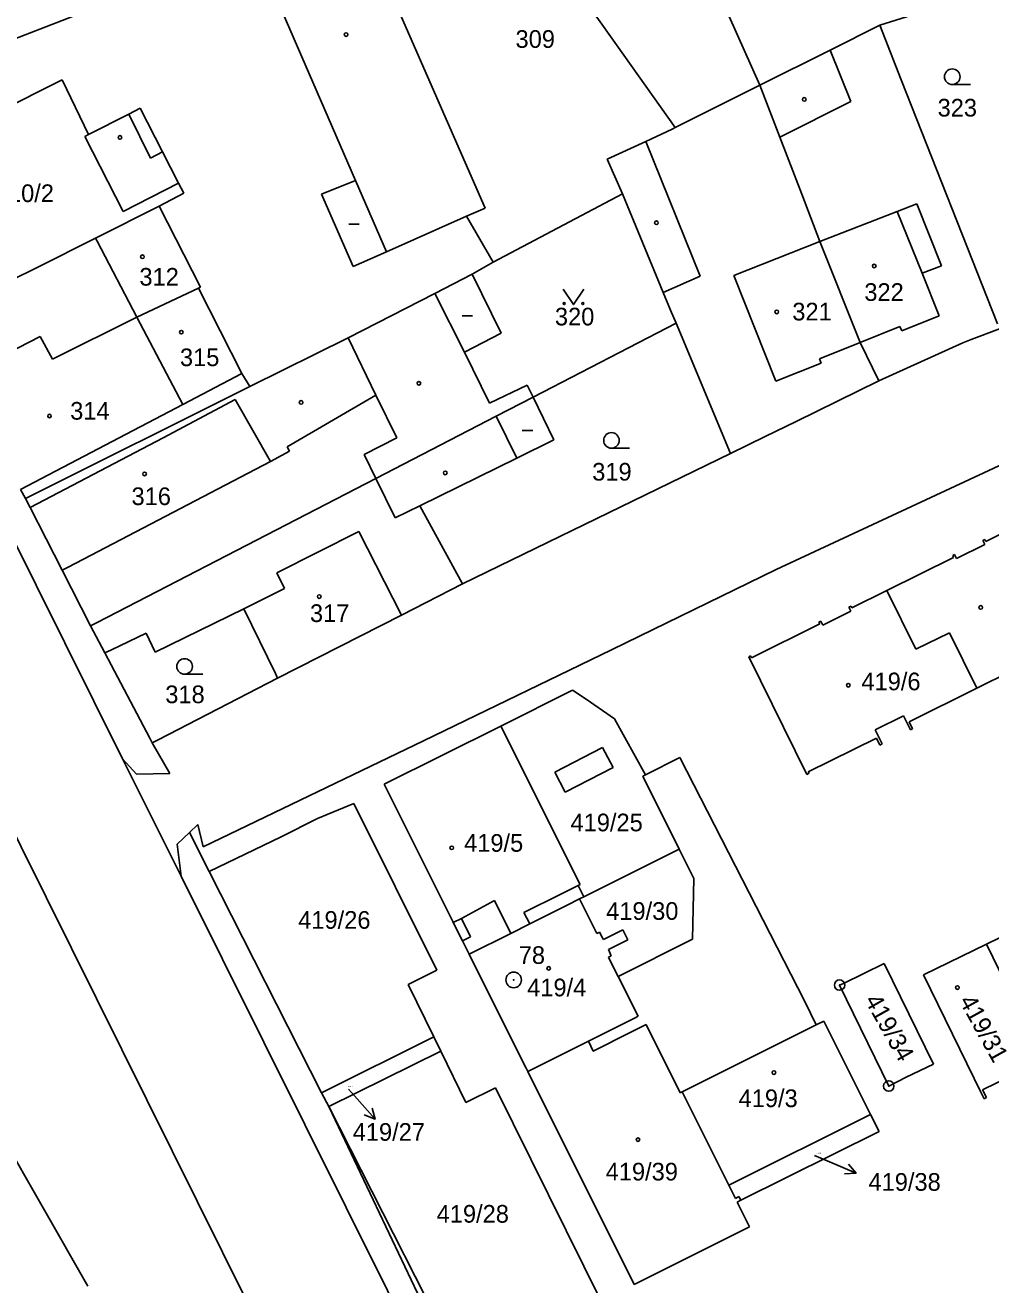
# Model space of a CAD drawing. Extents: x -736345 to -729997, y -1130177 to -1122501.
# Drawn here: x -733645.7 to -733552.8, y -1126760.8 to -1126639.6 of the extents above; entities that cross this region are included whole.
import ezdxf

# ---------------------------------------------------------------- set-up
doc = ezdxf.new("R2010")
doc.units = 0
for name, color, linetype in [('Vrstva 1', 7, 'Continuous'), ('Vrstva 16', 7, 'Continuous'), ('Vrstva 17', 7, 'Continuous'), ('Vrstva 18', 7, 'Continuous'), ('Vrstva 19', 7, 'Continuous'), ('Vrstva 25', 7, 'Continuous'), ('Vrstva 4', 7, 'Continuous')]:
    doc.layers.add(name, color=color, linetype=linetype)

msp = doc.modelspace()

# ---------------------------------------------------------------- linework, layer by layer
at = {"layer": 'Vrstva 1'}
for points in [[(-733601.42, -1126657.16), (-733617.83, -1126619.63)], [(-733582.38, -1126628.77), (-733575, -1126645.33)], [(-733583.13, -1126649.42), (-733597.4, -1126629.25)], [(-733556.36, -1126637.34), (-733563.45, -1126639.57)], [(-733563.45, -1126639.57), (-733568.23, -1126641.96)], [(-733563.45, -1126639.57), (-733561.38, -1126644.83)], [(-733568.23, -1126641.96), (-733575, -1126645.33)], [(-733642.11, -1126644.82), (-733660.73, -1126654.16)], [(-733639.58, -1126650.08), (-733642.11, -1126644.82)], [(-733575, -1126645.33), (-733583.13, -1126649.42)], [(-733575, -1126645.33), (-733573.08, -1126650.34)], [(-733561.38, -1126644.83), (-733552.13, -1126668.3)], [(-733635.72, -1126648.11), (-733639.58, -1126650.08)], [(-733634.61, -1126647.54), (-733635.72, -1126648.11)], [(-733632.46, -1126651.75), (-733634.61, -1126647.54)], [(-733583.13, -1126649.42), (-733583.44, -1126649.57)], [(-733585.97, -1126650.76), (-733589.67, -1126652.44)], [(-733583.44, -1126649.57), (-733585.97, -1126650.76)], [(-733573.08, -1126650.34), (-733570.96, -1126655.81)], [(-733630.92, -1126654.75), (-733632.46, -1126651.75)], [(-733589.67, -1126652.44), (-733588.21, -1126655.8)], [(-733664.04, -1126654.46), (-733636.32, -1126710.15)], [(-733630.42, -1126655.72), (-733630.92, -1126654.75)], [(-733632.78, -1126656.97), (-733630.42, -1126655.72)], [(-733600.64, -1126662.36), (-733588.21, -1126655.8)], [(-733588.21, -1126655.8), (-733584.3, -1126665.28)], [(-733570.96, -1126655.81), (-733569.22, -1126660.36)], [(-733638.9, -1126660.06), (-733632.78, -1126656.97)], [(-733632.78, -1126656.97), (-733628.8, -1126664.77)], [(-733601.42, -1126657.16), (-733603.21, -1126657.94)], [(-733603.21, -1126657.94), (-733600.64, -1126662.36)], [(-733644.46, -1126662.84), (-733638.9, -1126660.06)], [(-733638.76, -1126660.33), (-733638.9, -1126660.06)], [(-733634.94, -1126667.64), (-733638.76, -1126660.33)], [(-733569.22, -1126660.36), (-733565.34, -1126670.1)], [(-733647.06, -1126664.14), (-733644.46, -1126662.84)], [(-733600.64, -1126662.36), (-733602.67, -1126663.52)], [(-733602.67, -1126663.52), (-733606.27, -1126665.37)], [(-733602.67, -1126663.52), (-733599.87, -1126669.2)], [(-733629, -1126664.87), (-733634.94, -1126667.64)], [(-733628.8, -1126664.77), (-733629, -1126664.87)], [(-733624.82, -1126673.08), (-733629, -1126664.87)], [(-733584.3, -1126665.28), (-733583.58, -1126666.98)], [(-733606.27, -1126665.37), (-733614.62, -1126669.65)], [(-733634.94, -1126667.64), (-733630.52, -1126676.07)], [(-733583.58, -1126666.98), (-733583.04, -1126668.24)], [(-733583.04, -1126668.24), (-733596.81, -1126675.35)], [(-733583.04, -1126668.24), (-733577.83, -1126680.78)], [(-733554.65, -1126669.8), (-733551.94, -1126668.78)], [(-733614.62, -1126669.65), (-733624.06, -1126674.34)], [(-733599.87, -1126669.2), (-733603.42, -1126671.02)], [(-733565.34, -1126670.1), (-733563.55, -1126673.78)], [(-733563.55, -1126673.78), (-733555.47, -1126670.11)], [(-733555.47, -1126670.11), (-733554.65, -1126669.8)], [(-733603.42, -1126671.02), (-733600.99, -1126675.94)], [(-733630.52, -1126676.07), (-733624.82, -1126673.08)], [(-733624.82, -1126673.08), (-733624.06, -1126674.34)], [(-733571.51, -1126677.68), (-733563.55, -1126673.78)], [(-733624.06, -1126674.34), (-733645.66, -1126685.1)], [(-733600.99, -1126675.94), (-733597.37, -1126674.19)], [(-733597.37, -1126674.19), (-733596.81, -1126675.35)], [(-733596.81, -1126675.35), (-733600.37, -1126677.19)], [(-733594.82, -1126679.47), (-733596.81, -1126675.35)], [(-733600.37, -1126677.19), (-733611.95, -1126683.18)], [(-733574.49, -1126679.14), (-733571.51, -1126677.68)], [(-733598.38, -1126681.23), (-733594.82, -1126679.47)], [(-733577.83, -1126680.78), (-733574.49, -1126679.14)], [(-733547.38, -1126679.81), (-733573.41, -1126691.93)], [(-733603.59, -1126693.32), (-733577.83, -1126680.78)], [(-733607.71, -1126685.82), (-733598.38, -1126681.23)], [(-733611.95, -1126683.18), (-733638.77, -1126697.05)], [(-733646.12, -1126684.23), (-733645.66, -1126685.1)], [(-733645.66, -1126685.1), (-733645.21, -1126685.98)], [(-733603.59, -1126693.32), (-733607.71, -1126685.82)], [(-733645.21, -1126685.98), (-733642.13, -1126692)], [(-733553.26, -1126689.24), (-733546.65, -1126685.95)], [(-733556.06, -1126690.89), (-733553.34, -1126689.54)], [(-733553.53, -1126689.15), (-733553.35, -1126689.06)], [(-733553.34, -1126689.54), (-733553.53, -1126689.15)], [(-733553.35, -1126689.06), (-733553.26, -1126689.24)], [(-733556.35, -1126690.77), (-733562.77, -1126693.96)], [(-733556.44, -1126690.59), (-733556.26, -1126690.5)], [(-733556.35, -1126690.77), (-733556.44, -1126690.59)], [(-733556.26, -1126690.5), (-733556.06, -1126690.89)], [(-733573.41, -1126691.93), (-733589.27, -1126699.67)], [(-733642.13, -1126692), (-733639.39, -1126697.37)], [(-733609.47, -1126696.33), (-733603.59, -1126693.32)], [(-733566.14, -1126695.63), (-733562.77, -1126693.96)], [(-733559.97, -1126699.61), (-733562.77, -1126693.96)], [(-733566.42, -1126695.55), (-733566.22, -1126695.45)], [(-733566.23, -1126695.95), (-733566.42, -1126695.55)], [(-733566.22, -1126695.45), (-733566.14, -1126695.63)], [(-733633.17, -1126699.89), (-733624.63, -1126695.73)], [(-733624.63, -1126695.73), (-733621.61, -1126701.93)], [(-733621.39, -1126702.39), (-733609.47, -1126696.33)], [(-733568.94, -1126697.3), (-733566.23, -1126695.95)], [(-733638.77, -1126697.05), (-733639.39, -1126697.37)], [(-733639.39, -1126697.37), (-733638.01, -1126699.97)], [(-733575.79, -1126700.43), (-733569.23, -1126697.17)], [(-733569.32, -1126696.99), (-733569.14, -1126696.9)], [(-733569.23, -1126697.17), (-733569.32, -1126696.99)], [(-733569.14, -1126696.9), (-733568.94, -1126697.3)], [(-733556.75, -1126698.02), (-733559.97, -1126699.61)], [(-733554.1, -1126703.36), (-733556.75, -1126698.02)], [(-733637.39, -1126699.67), (-733634.03, -1126698.06)], [(-733634.03, -1126698.06), (-733633.17, -1126699.89)], [(-733638.01, -1126699.97), (-733637.39, -1126699.67)], [(-733638.01, -1126699.97), (-733633.69, -1126708.18)], [(-733589.27, -1126699.67), (-733607.36, -1126708.43)], [(-733576.06, -1126700.34), (-733575.88, -1126700.25)], [(-733570.46, -1126711.65), (-733576.06, -1126700.34)], [(-733575.88, -1126700.25), (-733575.79, -1126700.43)], [(-733632.88, -1126708.32), (-733621.39, -1126702.39)], [(-733621.61, -1126701.93), (-733621.39, -1126702.39)], [(-733550.89, -1126701.76), (-733554.1, -1126703.36)], [(-733617, -1126777.14), (-733653.37, -1126703.96)], [(-733599.9, -1126707), (-733593.02, -1126703.56)], [(-733593.02, -1126703.56), (-733591.71, -1126704.4)], [(-733554.1, -1126703.36), (-733560.62, -1126706.59)], [(-733591.71, -1126704.4), (-733588.97, -1126706.31)], [(-733588.97, -1126706.31), (-733585.99, -1126711.69)], [(-733561.18, -1126706.03), (-733563.89, -1126707.38)], [(-733560.51, -1126707.38), (-733561.18, -1126706.03)], [(-733611.13, -1126712.61), (-733599.9, -1126707)], [(-733599.9, -1126707), (-733592.28, -1126722.24)], [(-733563.89, -1126707.38), (-733563.22, -1126708.72)], [(-733560.62, -1126706.59), (-733560.29, -1126707.27)], [(-733560.29, -1126707.27), (-733560.51, -1126707.38)], [(-733633.69, -1126708.18), (-733633.46, -1126708.62)], [(-733633.46, -1126708.62), (-733632.88, -1126708.32)], [(-733631.75, -1126711.56), (-733633.46, -1126708.62)], [(-733607.36, -1126708.43), (-733628.57, -1126718.64)], [(-733563.77, -1126708.16), (-733570.33, -1126711.41)], [(-733563.44, -1126708.83), (-733563.77, -1126708.16)], [(-733563.22, -1126708.72), (-733563.44, -1126708.83)], [(-733636.32, -1126710.15), (-733634.96, -1126711.62), (-733631.75, -1126711.56)], [(-733630.68, -1126721.44), (-733636.32, -1126710.15)], [(-733585.99, -1126711.69), (-733582.69, -1126710.04)], [(-733570.68, -1126733.52), (-733582.69, -1126710.04)], [(-733585.99, -1126711.69), (-733586.26, -1126711.82)], [(-733586.26, -1126711.82), (-733582.75, -1126718.85)], [(-733570.26, -1126711.55), (-733570.46, -1126711.65)], [(-733570.33, -1126711.41), (-733570.26, -1126711.55)], [(-733604.54, -1126725.8), (-733611.13, -1126712.61)], [(-733617.56, -1126715.9), (-733614.06, -1126714.44)], [(-733614.06, -1126714.44), (-733606.07, -1126730.5)], [(-733621.05, -1126717.67), (-733617.56, -1126715.9)], [(-733629.87, -1126717.24), (-733631.05, -1126718.36)], [(-733629.87, -1126717.24), (-733629.06, -1126716.46)], [(-733629.87, -1126717.24), (-733627.99, -1126721)], [(-733628.57, -1126718.64), (-733629.06, -1126716.46)], [(-733630.68, -1126721.44), (-733631.05, -1126718.36)], [(-733627.99, -1126721), (-733621.05, -1126717.67)], [(-733591.92, -1126723.44), (-733582.75, -1126718.85)], [(-733582.75, -1126718.85), (-733581.34, -1126721.67)], [(-733617.18, -1126742.29), (-733627.99, -1126721)], [(-733630.68, -1126721.44), (-733590.98, -1126801.18)], [(-733592.28, -1126722.24), (-733592.47, -1126722.34)], [(-733581.34, -1126721.67), (-733581.48, -1126727.52)], [(-733597.69, -1126724.95), (-733594.08, -1126723.14)], [(-733594.08, -1126723.14), (-733592.47, -1126722.34)], [(-733591.92, -1126723.44), (-733592.34, -1126723.64)], [(-733603.7, -1126725.51), (-733600.53, -1126723.8)], [(-733600.53, -1126723.8), (-733598.96, -1126726.95)], [(-733593.53, -1126724.24), (-733597.14, -1126726.05)], [(-733592.34, -1126723.64), (-733593.53, -1126724.24)], [(-733592.34, -1126723.64), (-733590.68, -1126726.96)], [(-733553.2, -1126727.99), (-733546.01, -1126724.49)], [(-733604.49, -1126725.9), (-733604.54, -1126725.8)], [(-733604.49, -1126725.9), (-733603.7, -1126725.51)], [(-733603.61, -1126727.66), (-733604.49, -1126725.9)], [(-733597.14, -1126726.05), (-733597.69, -1126724.95)], [(-733598.96, -1126726.95), (-733597.14, -1126726.05)], [(-733590.68, -1126726.96), (-733590.42, -1126726.83)], [(-733590.42, -1126726.83), (-733590.33, -1126727.01)], [(-733590.33, -1126727.01), (-733590.19, -1126727.27)], [(-733590.05, -1126727.55), (-733588.19, -1126726.62)], [(-733588.19, -1126726.62), (-733587.71, -1126727.58)], [(-733602.96, -1126728.95), (-733603.61, -1126727.66)], [(-733590.19, -1126727.27), (-733590.05, -1126727.55)], [(-733587.71, -1126727.58), (-733589.57, -1126728.51)], [(-733588.63, -1126731.09), (-733581.48, -1126727.52)], [(-733559.24, -1126730.93), (-733553.2, -1126727.99)], [(-733553.2, -1126727.99), (-733550.12, -1126734.31)], [(-733602.82, -1126729.23), (-733602.96, -1126728.95)], [(-733597.47, -1126739.93), (-733602.82, -1126729.23)], [(-733589.57, -1126728.51), (-733589.29, -1126729.11)], [(-733589.29, -1126729.11), (-733589.54, -1126729.25)], [(-733589.54, -1126729.25), (-733588.74, -1126730.87)], [(-733606.07, -1126730.5), (-733608.83, -1126731.88)], [(-733566.96, -1126731.76), (-733563.02, -1126729.84)], [(-733563.02, -1126729.84), (-733558.3, -1126739.53)], [(-733608.83, -1126731.88), (-733606.37, -1126736.9)], [(-733588.74, -1126730.87), (-733588.63, -1126731.09)], [(-733588.63, -1126731.09), (-733586.69, -1126734.93)], [(-733567.32, -1126731.93), (-733566.96, -1126731.76)], [(-733562.59, -1126741.64), (-733567.32, -1126731.93)], [(-733554.37, -1126740.92), (-733559.24, -1126730.93)], [(-733570.68, -1126733.52), (-733569.56, -1126735.75)], [(-733587.89, -1126735.53), (-733591.49, -1126737.34)], [(-733587.05, -1126735.11), (-733587.89, -1126735.53)], [(-733586.69, -1126734.93), (-733587.05, -1126735.11)], [(-733568.84, -1126735.39), (-733569.56, -1126735.75)], [(-733564.35, -1126744.37), (-733568.84, -1126735.39)], [(-733585.94, -1126735.73), (-733587.42, -1126736.47), (-733591.03, -1126738.28), (-733591.49, -1126737.34)], [(-733585.94, -1126735.73), (-733582.66, -1126742.3)], [(-733606.37, -1126736.9), (-733617.18, -1126742.29)], [(-733606.37, -1126736.9), (-733605.69, -1126738.29)], [(-733591.49, -1126737.34), (-733597.31, -1126740.25)], [(-733652.34, -1126738.71), (-733639.66, -1126760.9)], [(-733616.47, -1126743.62), (-733605.69, -1126738.29)], [(-733605.69, -1126738.29), (-733603.27, -1126743.24)], [(-733597.31, -1126740.25), (-733597.47, -1126739.93)], [(-733597.31, -1126740.25), (-733587.07, -1126760.73)], [(-733558.3, -1126739.53), (-733560.91, -1126740.8)], [(-733549.51, -1126740.02), (-733553.56, -1126742)], [(-733560.91, -1126740.8), (-733562.59, -1126741.64)], [(-733553.79, -1126742.11), (-733554.37, -1126740.92)], [(-733616.47, -1126743.62), (-733617.18, -1126742.29)], [(-733603.27, -1126743.24), (-733600.44, -1126741.82)], [(-733600.44, -1126741.82), (-733588.52, -1126765.83)], [(-733582.66, -1126742.3), (-733582.48, -1126742.21)], [(-733577.99, -1126751.19), (-733582.48, -1126742.21)], [(-733553.42, -1126742.87), (-733553.79, -1126742.11)], [(-733553.56, -1126742), (-733553.19, -1126742.76)], [(-733553.19, -1126742.76), (-733553.42, -1126742.87)], [(-733601.94, -1126772.22), (-733616.47, -1126743.62)], [(-733616.47, -1126743.62), (-733602.44, -1126773.11)], [(-733577.99, -1126751.19), (-733564.35, -1126744.37)], [(-733564.35, -1126744.37), (-733563.52, -1126746.02)], [(-733563.52, -1126746.02), (-733576.82, -1126752.64)], [(-733577.35, -1126752.46), (-733577.99, -1126751.19)], [(-733577, -1126752.28), (-733577.35, -1126752.46)], [(-733576.82, -1126752.64), (-733577, -1126752.28)], [(-733577.18, -1126752.82), (-733576.82, -1126752.64)], [(-733576.88, -1126753.4), (-733577.18, -1126752.82)], [(-733575.99, -1126755.18), (-733576.88, -1126753.4)], [(-733587.07, -1126760.73), (-733575.99, -1126755.18)]]:
    msp.add_lwpolyline(points, dxfattribs=at)
at = {"layer": 'Vrstva 16'}
for points in [[(-733614.58, -1126741.94), (-733614, -1126742.59)], [(-733569.72, -1126748.34), (-733568.5, -1126748.85)]]:
    msp.add_lwpolyline(points, dxfattribs=at)
at = {"layer": 'Vrstva 25'}
for points in [[(-733556.48, -1126645.27), (-733554.73, -1126645.27)], [(-733614.54, -1126658.72), (-733613.54, -1126658.72)], [(-733593.92, -1126664.95), (-733592.92, -1126666.45), (-733591.92, -1126664.95)], [(-733603.64, -1126667.52), (-733602.64, -1126667.52)], [(-733597.85, -1126678.55), (-733596.85, -1126678.55)], [(-733589.27, -1126680.27), (-733587.52, -1126680.27)], [(-733630.34, -1126702.02), (-733628.59, -1126702.02)], [(-733614, -1126742.59), (-733612.017, -1126744.84)], [(-733612.303, -1126743.759), (-733612.017, -1126744.84), (-733613.053, -1126744.42)], [(-733568.5, -1126748.85), (-733565.737, -1126750.017)], [(-733566.464, -1126749.167), (-733565.737, -1126750.017), (-733566.853, -1126750.088)]]:
    msp.add_lwpolyline(points, dxfattribs=at)
for centre, radius in [((-733614.8, -1126640.46), 0.175), ((-733556.48, -1126644.52), 0.75), ((-733570.72, -1126646.7), 0.175), ((-733636.56, -1126650.36), 0.175), ((-733584.94, -1126658.57), 0.175), ((-733634.4, -1126661.84), 0.175), ((-733563.99, -1126662.73), 0.175), ((-733593.82, -1126666.35), 0.1), ((-733592.02, -1126666.35), 0.1), ((-733573.37, -1126667.15), 0.175), ((-733630.66, -1126669.1), 0.175), ((-733607.8, -1126674.02), 0.175), ((-733619.13, -1126675.86), 0.175), ((-733643.34, -1126677.17), 0.175), ((-733589.27, -1126679.52), 0.75), ((-733634.19, -1126682.74), 0.175), ((-733605.26, -1126682.64), 0.175), ((-733617.39, -1126694.54), 0.175), ((-733553.74, -1126695.59), 0.175), ((-733630.34, -1126701.27), 0.75), ((-733566.48, -1126703.07), 0.175), ((-733604.64, -1126718.72), 0.175), ((-733598.68, -1126731.43), 0.75), ((-733595.31, -1126730.32), 0.175), ((-733598.68, -1126731.43), 0.032), ((-733567.32, -1126731.93), 0.5), ((-733567.32, -1126731.93), 0.032), ((-733555.98, -1126732.17), 0.175), ((-733573.64, -1126740.35), 0.175), ((-733562.59, -1126741.64), 0.5), ((-733562.59, -1126741.64), 0.032), ((-733586.72, -1126746.8), 0.175)]:
    msp.add_circle(centre, radius, dxfattribs=at)
at = {"layer": 'Vrstva 4'}
for points in [[(-733627.7, -1126622.7), (-733613.91, -1126654.5)], [(-733648.86, -1126641.72), (-733641.13, -1126638.72)], [(-733568.23, -1126641.96), (-733566.24, -1126646.91)], [(-733566.24, -1126646.91), (-733573.08, -1126650.34)], [(-733635.72, -1126648.11), (-733633.62, -1126652.34)], [(-733639.95, -1126650.27), (-733639.58, -1126650.08)], [(-733636.26, -1126657.48), (-733639.95, -1126650.27)], [(-733585.97, -1126650.76), (-733580.73, -1126663.7)], [(-733633.62, -1126652.34), (-733632.46, -1126651.75)], [(-733630.92, -1126654.75), (-733636.26, -1126657.48)], [(-733613.91, -1126654.5), (-733617.18, -1126655.83)], [(-733613.91, -1126654.5), (-733610.93, -1126661.37)], [(-733617.18, -1126655.83), (-733614.11, -1126662.77)], [(-733559.88, -1126656.75), (-733561.78, -1126657.49)], [(-733557.51, -1126662.71), (-733559.88, -1126656.75)], [(-733610.93, -1126661.37), (-733603.21, -1126657.94)], [(-733569.22, -1126660.36), (-733561.78, -1126657.49)], [(-733561.78, -1126657.49), (-733559.38, -1126663.43)], [(-733569.22, -1126660.36), (-733577.51, -1126663.65)], [(-733614.11, -1126662.77), (-733610.93, -1126661.37)], [(-733559.38, -1126663.43), (-733557.51, -1126662.71)], [(-733580.73, -1126663.7), (-733584.3, -1126665.28)], [(-733577.51, -1126663.65), (-733573.47, -1126673.81)], [(-733559.38, -1126663.43), (-733557.73, -1126667.54)], [(-733606.27, -1126665.37), (-733603.42, -1126671.02)], [(-733634.94, -1126667.64), (-733643.04, -1126671.69)], [(-733557.73, -1126667.54), (-733561.33, -1126668.97)], [(-733561.51, -1126668.54), (-733565.34, -1126670.1)], [(-733561.33, -1126668.97), (-733561.51, -1126668.54)], [(-733644.25, -1126669.52), (-733651.75, -1126673.37)], [(-733643.04, -1126671.69), (-733644.25, -1126669.52)], [(-733611.95, -1126675.17), (-733614.62, -1126669.65)], [(-733569.26, -1126671.65), (-733565.34, -1126670.1)], [(-733573.47, -1126673.81), (-733569.1, -1126672.07)], [(-733569.1, -1126672.07), (-733569.26, -1126671.65)], [(-733630.52, -1126676.07), (-733646.12, -1126684.23)], [(-733632.4, -1126679.27), (-733625.47, -1126675.59)], [(-733625.47, -1126675.59), (-733622.08, -1126681.54)], [(-733620.48, -1126680.12), (-733611.95, -1126675.17)], [(-733611.95, -1126675.17), (-733609.93, -1126679.28)], [(-733600.37, -1126677.19), (-733598.38, -1126681.23)], [(-733645.21, -1126685.98), (-733632.4, -1126679.27)], [(-733609.93, -1126679.28), (-733613.08, -1126680.87)], [(-733622.08, -1126681.54), (-733620.26, -1126680.56)], [(-733620.26, -1126680.56), (-733620.48, -1126680.12)], [(-733613.08, -1126680.87), (-733611.95, -1126683.18)], [(-733622.08, -1126681.54), (-733641.56, -1126691.7)], [(-733610.08, -1126686.98), (-733611.95, -1126683.18)], [(-733607.71, -1126685.82), (-733610.08, -1126686.98)], [(-733621.48, -1126692.26), (-733613.59, -1126688.28)], [(-733613.59, -1126688.28), (-733609.47, -1126696.33)], [(-733641.56, -1126691.7), (-733642.13, -1126692)], [(-733620.72, -1126693.76), (-733621.48, -1126692.26)], [(-733624.63, -1126695.73), (-733620.72, -1126693.76)], [(-733590.12, -1126709.06), (-733594.72, -1126711.43)], [(-733589.11, -1126711), (-733590.12, -1126709.06)], [(-733593.71, -1126713.38), (-733589.11, -1126711)], [(-733594.72, -1126711.43), (-733593.71, -1126713.38)], [(-733592.47, -1126722.34), (-733591.92, -1126723.44)], [(-733603.7, -1126725.51), (-733602.82, -1126727.27)], [(-733598.96, -1126726.95), (-733602.96, -1126728.95)], [(-733602.82, -1126727.27), (-733603.61, -1126727.66)], [(-733569.56, -1126735.75), (-733582.48, -1126742.21)]]:
    msp.add_lwpolyline(points, dxfattribs=at)

# ---------------------------------------------------------------- texts
at = {"layer": 'Vrstva 16'}
for s, p in [('419/27', (-733614.168, -1126746.91)), ('419/38', (-733564.54, -1126751.72))]:
    msp.add_text(s, height=1.7, dxfattribs=at).set_placement(p)
at = {"layer": 'Vrstva 17'}
msp.add_text('78', height=1.7, dxfattribs=at).set_placement((-733598.19, -1126729.89))
at = {"layer": 'Vrstva 18'}
for s, height, p in [('309', 1.7, (-733598.5, -1126641.74)), ('323', 1.7, (-733557.89, -1126648.35)), ('320', 1.7, (-733594.71, -1126668.45)), ('319', 1.7, (-733591.12, -1126683.38)), ('318', 1.7, (-733632.2, -1126704.8)), ('419/25', 1.7, (-733593.21, -1126717.13)), ('419/30', 1.7, (-733589.78, -1126725.65)), ('419/26', 1.7, (-733619.41, -1126726.51)), ('419/27', 0.1, (-733614.594, -1126741.74)), ('419/38', 0.1, (-733569.52, -1126748.14)), ('419/28', 1.7, (-733606.09, -1126754.79))]:
    msp.add_text(s, height=height, dxfattribs=at).set_placement(p)
msp.add_text('419/34', height=1.7, rotation=299.40238, dxfattribs=at).set_placement((-733564.958, -1126733.386))
at = {"layer": 'Vrstva 19'}
for s, p in [('310/2', (-733648.6, -1126656.58)), ('312', (-733634.69, -1126664.62)), ('322', (-733564.94, -1126666.09)), ('321', (-733571.87, -1126667.97)), ('315', (-733630.79, -1126672.37)), ('314', (-733641.35, -1126677.52)), ('316', (-733635.45, -1126685.74)), ('317', (-733618.28, -1126696.99)), ('419/6', (-733565.22, -1126703.56)), ('419/5', (-733603.45, -1126719.1)), ('419/4', (-733597.38, -1126733.01)), ('419/3', (-733577.04, -1126743.67)), ('419/39', (-733589.828, -1126750.73))]:
    msp.add_text(s, height=1.7, dxfattribs=at).set_placement(p)
msp.add_text('419/31', height=1.7, rotation=299.00238, dxfattribs=at).set_placement((-733555.859, -1126733.457))

doc.saveas('drawing.dxf')
